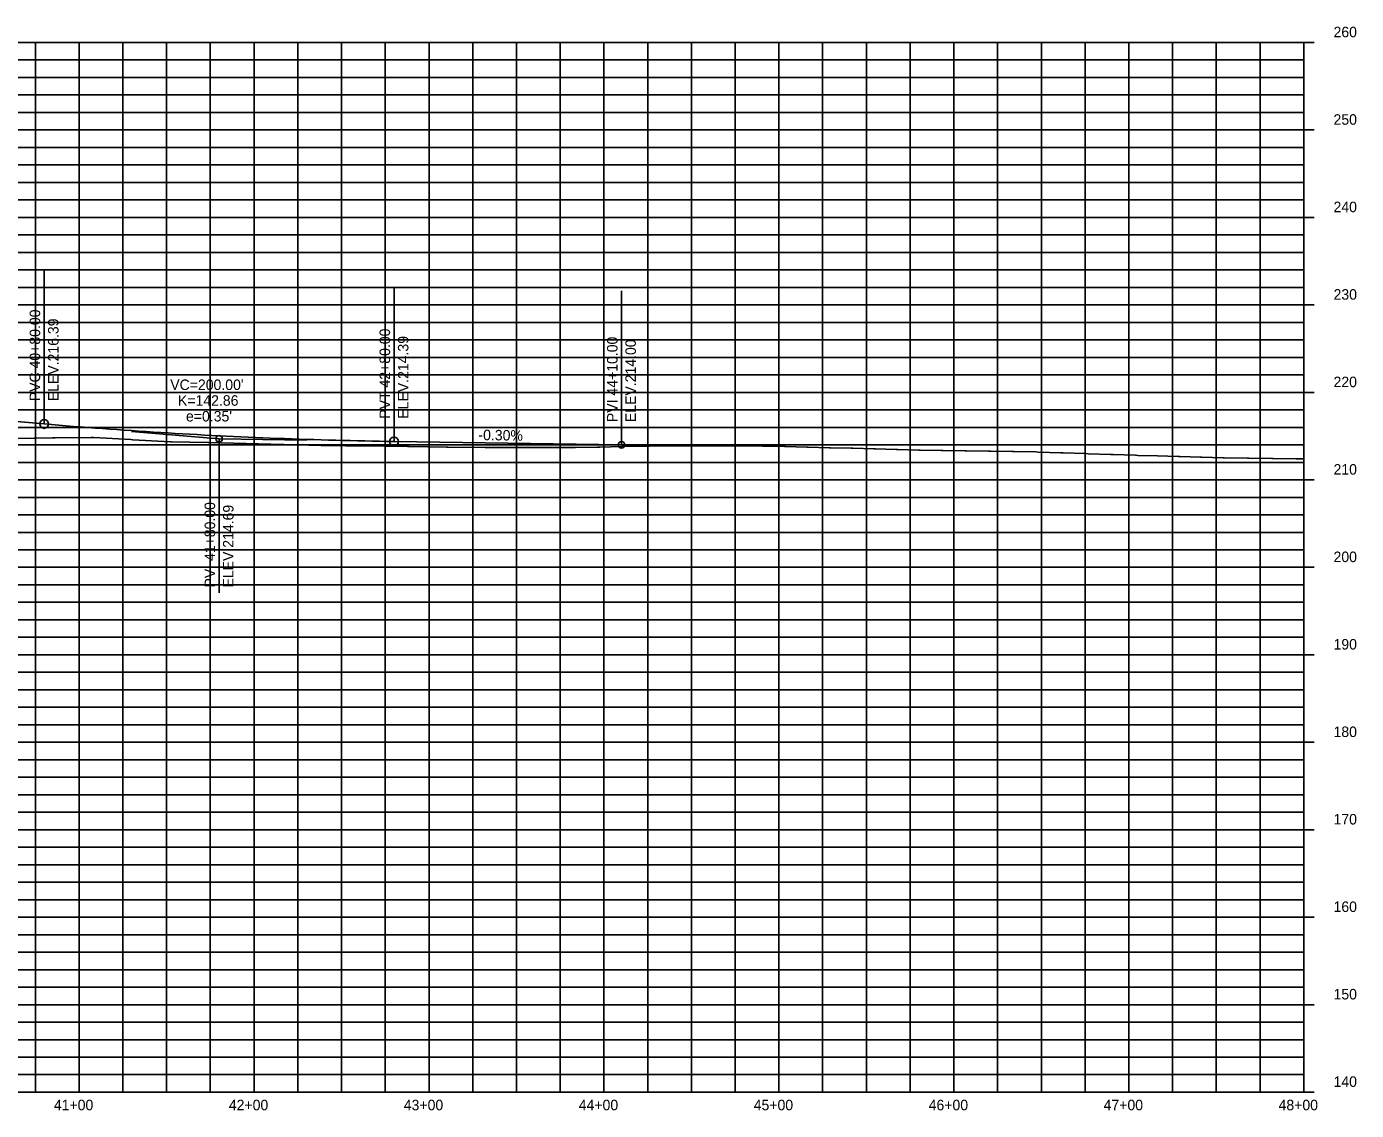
# Model space of a CAD drawing. Extents: x 1732967 to 1742744, y 374025 to 374739.
# Drawn here: x 1736327 to 1737087, y 374119 to 374739 of the extents above; entities that cross this region are included whole.
import ezdxf

# ---------------------------------------------------------------- set-up
doc = ezdxf.new("R2010")
doc.units = 0
for name, color, linetype in [('R_Axis_Annotation', 7, 'Continuous'), ('R_Exist Surface', 7, 'Continuous'), ('R_Grid', 7, 'Continuous'), ('R_Grid Annot', 7, 'Continuous'), ('R_Grid_Minor', 7, 'Continuous'), ('R_Vert Alg', 7, 'Continuous'), ('R_Vert Alg Annot', 7, 'Continuous')]:
    doc.layers.add(name, color=color, linetype=linetype)

msp = doc.modelspace()

# ---------------------------------------------------------------- linework, layer by layer
at = {"layer": 'R_Exist Surface'}
msp.add_lwpolyline([(1736321.43, 374503.33), (1736341.99, 374503.59), (1736343.42, 374503.6), (1736364.06, 374503.86), (1736365.53, 374503.78), (1736386.72, 374502.62), (1736387.81, 374502.55), (1736409.37, 374501.37), (1736410.02, 374501.37), (1736430.87, 374500.9), (1736431.31, 374500.89), (1736452.37, 374500.42), (1736452.59, 374500.41), (1736473.87, 374499.87), (1736474.17, 374499.86), (1736495.37, 374499.32), (1736509.4, 374499.13), (1736520.16, 374498.98), (1736520.48, 374498.98), (1736544.93, 374498.64), (1736545.87, 374498.63), (1736567.14, 374498.34), (1736567.99, 374498.33), (1736589.34, 374498.03), (1736589.79, 374498.03), (1736602.23, 374498.03), (1736602.82, 374498.03), (1736615.11, 374498.04), (1736615.86, 374498.03), (1736628, 374498.04), (1736628.91, 374498.03), (1736640.89, 374498.04), (1736653.42, 374498.3), (1736654.16, 374498.31), (1736654.9, 374498.32), (1736667.45, 374498.59), (1736667.86, 374498.59), (1736680.74, 374498.88), (1736680.81, 374498.88), (1736683.24, 374498.93), (1736693.8, 374499.14), (1736694.03, 374499.14), (1736707.36, 374499.1), (1736707.46, 374499.1), (1736716.62, 374499.07), (1736720.89, 374499.05), (1736720.95, 374499.05), (1736734.32, 374498.98), (1736734.57, 374498.98), (1736747.75, 374498.92), (1736748.15, 374498.91), (1736760.45, 374498.61), (1736760.99, 374498.59), (1736773.15, 374498.29), (1736773.83, 374498.27), (1736785.85, 374497.98), (1736786.66, 374497.96), (1736798.54, 374497.66), (1736799.51, 374497.65), (1736811.38, 374497.33), (1736812.33, 374497.31), (1736824.22, 374497), (1736825.14, 374496.98), (1736837.06, 374496.66), (1736837.96, 374496.65), (1736849.9, 374496.33), (1736850.82, 374496.32), (1736863.44, 374496.13), (1736864.44, 374496.12), (1736876.99, 374495.94), (1736878.05, 374495.93), (1736890.53, 374495.75), (1736891.67, 374495.73), (1736904.07, 374495.55), (1736905.35, 374495.51), (1736918.28, 374495.07), (1736919.61, 374495.03), (1736932.48, 374494.59), (1736933.87, 374494.55), (1736946.69, 374494.12), (1736948.14, 374494.07), (1736960.9, 374493.64), (1736962.25, 374493.61), (1736973.6, 374493.29), (1736985.28, 374492.97), (1736986.29, 374492.95), (1736998.15, 374492.62), (1736998.99, 374492.6), (1737011.03, 374492.27), (1737011.68, 374492.26), (1737024.91, 374492.06), (1737025.69, 374492.04), (1737038.84, 374491.84), (1737039.7, 374491.83), (1737052.78, 374491.63), (1737053.71, 374491.62), (1737057.17, 374491.57)], dxfattribs=at)
at = {"layer": 'R_Grid'}
for p, q in [((1734257.17, 374729.61), (1737057.17, 374729.61)), ((1734257.17, 374729.61), (1737057.17, 374729.61)), ((1736357.17, 374129.61), (1736357.17, 374729.61)), ((1736457.17, 374129.61), (1736457.17, 374729.61)), ((1736557.17, 374129.61), (1736557.17, 374729.61)), ((1736657.17, 374129.61), (1736657.17, 374729.61)), ((1736757.17, 374129.61), (1736757.17, 374729.61)), ((1736857.17, 374129.61), (1736857.17, 374729.61)), ((1736957.17, 374129.61), (1736957.17, 374729.61)), ((1737057.17, 374129.61), (1737057.17, 374729.61)), ((1734257.17, 374679.61), (1737057.17, 374679.61)), ((1734257.17, 374629.61), (1737057.17, 374629.61)), ((1734257.17, 374579.61), (1737057.17, 374579.61)), ((1734257.17, 374529.61), (1737057.17, 374529.61)), ((1734257.17, 374479.61), (1737057.17, 374479.61)), ((1734257.17, 374429.61), (1737057.17, 374429.61)), ((1734257.17, 374379.61), (1737057.17, 374379.61)), ((1734257.17, 374329.61), (1737057.17, 374329.61)), ((1734257.17, 374279.61), (1737057.17, 374279.61)), ((1734257.17, 374229.61), (1737057.17, 374229.61)), ((1734257.17, 374179.61), (1737057.17, 374179.61)), ((1734257.17, 374129.61), (1737057.17, 374129.61))]:
    msp.add_line(p, q, dxfattribs=at)
at = {"layer": 'R_Grid Annot'}
for p, q in [((1737063.17, 374729.61), (1737057.17, 374729.61)), ((1737063.17, 374729.61), (1737057.17, 374729.61)), ((1737057.17, 374719.61), (1737054.17, 374719.61)), ((1737057.17, 374709.61), (1737054.17, 374709.61)), ((1737057.17, 374699.61), (1737054.17, 374699.61)), ((1737057.17, 374689.61), (1737054.17, 374689.61)), ((1737063.17, 374679.61), (1737057.17, 374679.61)), ((1737057.17, 374669.61), (1737054.17, 374669.61)), ((1737057.17, 374659.61), (1737054.17, 374659.61)), ((1737057.17, 374649.61), (1737054.17, 374649.61)), ((1737057.17, 374639.61), (1737054.17, 374639.61)), ((1737063.17, 374629.61), (1737057.17, 374629.61)), ((1737057.17, 374619.61), (1737054.17, 374619.61)), ((1737057.17, 374609.61), (1737054.17, 374609.61)), ((1737057.17, 374599.61), (1737054.17, 374599.61)), ((1737057.17, 374589.61), (1737054.17, 374589.61)), ((1737063.17, 374579.61), (1737057.17, 374579.61)), ((1737057.17, 374569.61), (1737054.17, 374569.61)), ((1737057.17, 374559.61), (1737054.17, 374559.61)), ((1737057.17, 374549.61), (1737054.17, 374549.61)), ((1737057.17, 374539.61), (1737054.17, 374539.61)), ((1737063.17, 374529.61), (1737057.17, 374529.61)), ((1737057.17, 374519.61), (1737054.17, 374519.61)), ((1737057.17, 374509.61), (1737054.17, 374509.61)), ((1737057.17, 374499.61), (1737054.17, 374499.61)), ((1737057.17, 374489.61), (1737054.17, 374489.61)), ((1737063.17, 374479.61), (1737057.17, 374479.61)), ((1737057.17, 374469.61), (1737054.17, 374469.61)), ((1737057.17, 374459.61), (1737054.17, 374459.61)), ((1737057.17, 374449.61), (1737054.17, 374449.61)), ((1737057.17, 374439.61), (1737054.17, 374439.61)), ((1737063.17, 374429.61), (1737057.17, 374429.61)), ((1737057.17, 374419.61), (1737054.17, 374419.61)), ((1737057.17, 374409.61), (1737054.17, 374409.61)), ((1737057.17, 374399.61), (1737054.17, 374399.61)), ((1737057.17, 374389.61), (1737054.17, 374389.61)), ((1737063.17, 374379.61), (1737057.17, 374379.61)), ((1737057.17, 374369.61), (1737054.17, 374369.61)), ((1737057.17, 374359.61), (1737054.17, 374359.61)), ((1737057.17, 374349.61), (1737054.17, 374349.61)), ((1737057.17, 374339.61), (1737054.17, 374339.61)), ((1737063.17, 374329.61), (1737057.17, 374329.61)), ((1737057.17, 374319.61), (1737054.17, 374319.61)), ((1737057.17, 374309.61), (1737054.17, 374309.61)), ((1737057.17, 374299.61), (1737054.17, 374299.61)), ((1737057.17, 374289.61), (1737054.17, 374289.61)), ((1737063.17, 374279.61), (1737057.17, 374279.61)), ((1737057.17, 374269.61), (1737054.17, 374269.61)), ((1737057.17, 374259.61), (1737054.17, 374259.61)), ((1737057.17, 374249.61), (1737054.17, 374249.61)), ((1737057.17, 374239.61), (1737054.17, 374239.61)), ((1737063.17, 374229.61), (1737057.17, 374229.61)), ((1737057.17, 374219.61), (1737054.17, 374219.61)), ((1737057.17, 374209.61), (1737054.17, 374209.61)), ((1737057.17, 374199.61), (1737054.17, 374199.61)), ((1737057.17, 374189.61), (1737054.17, 374189.61)), ((1737063.17, 374179.61), (1737057.17, 374179.61)), ((1737057.17, 374169.61), (1737054.17, 374169.61)), ((1737057.17, 374159.61), (1737054.17, 374159.61)), ((1737057.17, 374149.61), (1737054.17, 374149.61)), ((1737057.17, 374139.61), (1737054.17, 374139.61)), ((1737063.17, 374129.61), (1737057.17, 374129.61))]:
    msp.add_line(p, q, dxfattribs=at)
at = {"layer": 'R_Grid_Minor'}
for p, q in [((1736332.17, 374129.61), (1736332.17, 374729.61)), ((1736382.17, 374129.61), (1736382.17, 374729.61)), ((1736407.17, 374129.61), (1736407.17, 374729.61)), ((1736432.17, 374129.61), (1736432.17, 374729.61)), ((1736482.17, 374129.61), (1736482.17, 374729.61)), ((1736507.17, 374129.61), (1736507.17, 374729.61)), ((1736532.17, 374129.61), (1736532.17, 374729.61)), ((1736582.17, 374129.61), (1736582.17, 374729.61)), ((1736607.17, 374129.61), (1736607.17, 374729.61)), ((1736632.17, 374129.61), (1736632.17, 374729.61)), ((1736682.17, 374129.61), (1736682.17, 374729.61)), ((1736707.17, 374129.61), (1736707.17, 374729.61)), ((1736732.17, 374129.61), (1736732.17, 374729.61)), ((1736782.17, 374129.61), (1736782.17, 374729.61)), ((1736807.17, 374129.61), (1736807.17, 374729.61)), ((1736832.17, 374129.61), (1736832.17, 374729.61)), ((1736882.17, 374129.61), (1736882.17, 374729.61)), ((1736907.17, 374129.61), (1736907.17, 374729.61)), ((1736932.17, 374129.61), (1736932.17, 374729.61)), ((1736982.17, 374129.61), (1736982.17, 374729.61)), ((1737007.17, 374129.61), (1737007.17, 374729.61)), ((1737032.17, 374129.61), (1737032.17, 374729.61)), ((1734257.17, 374719.61), (1737057.17, 374719.61)), ((1734257.17, 374709.61), (1737057.17, 374709.61)), ((1734257.17, 374699.61), (1737057.17, 374699.61)), ((1734257.17, 374689.61), (1737057.17, 374689.61)), ((1734257.17, 374669.61), (1737057.17, 374669.61)), ((1734257.17, 374659.61), (1737057.17, 374659.61)), ((1734257.17, 374649.61), (1737057.17, 374649.61)), ((1734257.17, 374639.61), (1737057.17, 374639.61)), ((1734257.17, 374619.61), (1737057.17, 374619.61)), ((1734257.17, 374609.61), (1737057.17, 374609.61)), ((1734257.17, 374599.61), (1737057.17, 374599.61)), ((1734257.17, 374589.61), (1737057.17, 374589.61)), ((1734257.17, 374569.61), (1737057.17, 374569.61)), ((1734257.17, 374559.61), (1737057.17, 374559.61)), ((1734257.17, 374549.61), (1737057.17, 374549.61)), ((1734257.17, 374539.61), (1737057.17, 374539.61)), ((1734257.17, 374519.61), (1737057.17, 374519.61)), ((1734257.17, 374509.61), (1737057.17, 374509.61)), ((1734257.17, 374499.61), (1737057.17, 374499.61)), ((1734257.17, 374489.61), (1737057.17, 374489.61)), ((1734257.17, 374469.61), (1737057.17, 374469.61)), ((1734257.17, 374459.61), (1737057.17, 374459.61)), ((1734257.17, 374449.61), (1737057.17, 374449.61)), ((1734257.17, 374439.61), (1737057.17, 374439.61)), ((1734257.17, 374419.61), (1737057.17, 374419.61)), ((1734257.17, 374409.61), (1737057.17, 374409.61)), ((1734257.17, 374399.61), (1737057.17, 374399.61)), ((1734257.17, 374389.61), (1737057.17, 374389.61)), ((1734257.17, 374369.61), (1737057.17, 374369.61)), ((1734257.17, 374359.61), (1737057.17, 374359.61)), ((1734257.17, 374349.61), (1737057.17, 374349.61)), ((1734257.17, 374339.61), (1737057.17, 374339.61)), ((1734257.17, 374319.61), (1737057.17, 374319.61)), ((1734257.17, 374309.61), (1737057.17, 374309.61)), ((1734257.17, 374299.61), (1737057.17, 374299.61)), ((1734257.17, 374289.61), (1737057.17, 374289.61)), ((1734257.17, 374269.61), (1737057.17, 374269.61)), ((1734257.17, 374259.61), (1737057.17, 374259.61)), ((1734257.17, 374249.61), (1737057.17, 374249.61)), ((1734257.17, 374239.61), (1737057.17, 374239.61)), ((1734257.17, 374219.61), (1737057.17, 374219.61)), ((1734257.17, 374209.61), (1737057.17, 374209.61)), ((1734257.17, 374199.61), (1737057.17, 374199.61)), ((1734257.17, 374189.61), (1737057.17, 374189.61)), ((1734257.17, 374169.61), (1737057.17, 374169.61)), ((1734257.17, 374159.61), (1737057.17, 374159.61)), ((1734257.17, 374149.61), (1737057.17, 374149.61)), ((1734257.17, 374139.61), (1737057.17, 374139.61))]:
    msp.add_line(p, q, dxfattribs=at)
at = {"layer": 'R_Vert Alg'}
for p, q in [((1736317.17, 374513.26), (1736337.17, 374511.56)), ((1736537.17, 374501.56), (1736667.17, 374499.61))]:
    msp.add_line(p, q, dxfattribs=at)
msp.add_lwpolyline([(1736337.17, 374511.56), (1736341.33, 374511.21), (1736345.5, 374510.87), (1736349.67, 374510.53), (1736353.83, 374510.2), (1736358, 374509.87), (1736362.17, 374509.55), (1736366.33, 374509.23), (1736370.5, 374508.92), (1736374.67, 374508.62), (1736378.83, 374508.33), (1736383, 374508.04), (1736387.17, 374507.75), (1736391.33, 374507.47), (1736395.5, 374507.2), (1736399.67, 374506.93), (1736403.83, 374506.67), (1736408, 374506.42), (1736412.17, 374506.17), (1736416.33, 374505.93), (1736420.5, 374505.7), (1736424.67, 374505.47), (1736428.83, 374505.24), (1736433, 374505.03), (1736441.33, 374504.61), (1736445.5, 374504.41), (1736449.67, 374504.22), (1736453.83, 374504.03), (1736458, 374503.85), (1736462.17, 374503.67), (1736466.33, 374503.5), (1736470.5, 374503.34), (1736474.67, 374503.18), (1736478.83, 374503.03), (1736483, 374502.89), (1736487.17, 374502.75), (1736491.33, 374502.62), (1736495.5, 374502.49), (1736499.67, 374502.37), (1736503.83, 374502.26), (1736508, 374502.15), (1736512.17, 374502.05), (1736516.33, 374501.95), (1736520.5, 374501.86), (1736524.67, 374501.78), (1736528.83, 374501.7), (1736533, 374501.63), (1736537.17, 374501.56)], dxfattribs=at)
at = {"layer": 'R_Vert Alg Annot'}
for p, q in [((1736337.17, 374521.56), (1736337.17, 374599.56)), ((1736537.17, 374511.56), (1736537.17, 374589.56)), ((1736667.17, 374509.61), (1736667.17, 374587.61)), ((1736337.17, 374511.56), (1736337.17, 374521.56)), ((1736537.17, 374501.56), (1736537.17, 374511.56)), ((1736667.17, 374499.61), (1736667.17, 374509.61)), ((1736387.17, 374507.31), (1736437.17, 374503.06)), ((1736437.17, 374503.06), (1736487.17, 374502.31)), ((1736437.17, 374503.06), (1736437.17, 374493.06)), ((1736437.17, 374493.06), (1736437.17, 374415.06))]:
    msp.add_line(p, q, dxfattribs=at)
for centre, radius in [((1736337.17, 374511.56), 2.5), ((1736437.17, 374503.06), 1.85), ((1736537.17, 374501.56), 2.5), ((1736667.17, 374499.61), 1.85)]:
    msp.add_circle(centre, radius, dxfattribs=at)

# ---------------------------------------------------------------- texts
at = {"layer": 'R_Axis_Annotation'}
for s, p in [('260', (1737074.18, 374732.61)), ('260', (1737074.18, 374732.61)), ('250', (1737074.18, 374682.61)), ('240', (1737074.18, 374632.61)), ('230', (1737074.18, 374582.61)), ('220', (1737074.18, 374532.61)), ('210', (1737074.18, 374482.61)), ('200', (1737074.18, 374432.61)), ('190', (1737074.18, 374382.61)), ('180', (1737074.18, 374332.61)), ('170', (1737074.18, 374282.61)), ('160', (1737074.18, 374232.61)), ('150', (1737074.18, 374182.61)), ('140', (1737074.18, 374132.61)), ('41+00', (1736342.76, 374119.26)), ('42+00', (1736442.76, 374119.26)), ('43+00', (1736542.76, 374119.26)), ('44+00', (1736642.76, 374119.26)), ('45+00', (1736742.76, 374119.26)), ('46+00', (1736842.76, 374119.26)), ('47+00', (1736942.76, 374119.26)), ('48+00', (1737042.76, 374119.26))]:
    msp.add_text(s, height=6, dxfattribs=at).set_placement(p)
at = {"layer": 'R_Vert Alg Annot'}
for s, rotation, p in [('PVC 40+80.00', 90, (1736334.92, 374524.56)), ('ELEV.216.39', 90, (1736345.42, 374524.56)), ('PVT 42+80.00', 90, (1736534.92, 374514.56)), ('ELEV.214.39', 90, (1736545.42, 374514.56)), ('PVI 44+10.00', 90, (1736664.92, 374512.61)), ('ELEV.214.00', 90, (1736675.42, 374512.61)), ('-0.30%', 359.14063, (1736585.39, 374502.34)), ('PVI 41+80.00', 90, (1736434.92, 374418.06)), ('ELEV.214.69', 90, (1736445.42, 374418.06))]:
    msp.add_text(s, height=6, rotation=rotation, dxfattribs=at).set_placement(p)
for s, p in [("VC=200.00'", (1736409.27, 374530.98)), ('K=142.86', (1736413.69, 374521.98)), ("e=0.35'", (1736418.27, 374512.98))]:
    msp.add_text(s, height=6, dxfattribs=at).set_placement(p)

doc.saveas('drawing.dxf')
